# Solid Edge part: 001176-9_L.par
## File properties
Last saved by: morva
Revision: 82
Accuracy: 0.990
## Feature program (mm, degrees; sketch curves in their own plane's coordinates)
body "unnamed Body 1"
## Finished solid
Body 1: solid body, 69 faces, 173 edges, 106 vertices.
  Faces by surface: torus 36, cylinder 23, cone 6, plane 4
  Edges by curve: circle 88, spline 44, line 33, curve on surface 8
Bounding box of the edges (mm; curved faces can reach further): 15.517 x 15.194 x 10.880, from (515.3001, 405.1641, -54.6746) to (530.8166, 420.3579, -43.7951).
Cylindrical faces by radius (mm): R0.5 x9, R3 x9, R7.5 x5
Conical faces (half-angle, radius in mm at the cone's reference point): 45 deg R4 x6
Toroidal faces (ring radius, tube radius in mm): R0.3 r0.2 x18, R3.2 r0.2 x10, R7.3 r0.2 x8
Planar faces by outward normal: oblique 4
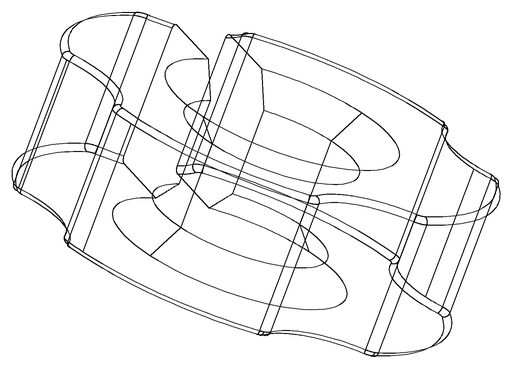
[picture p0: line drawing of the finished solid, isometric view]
